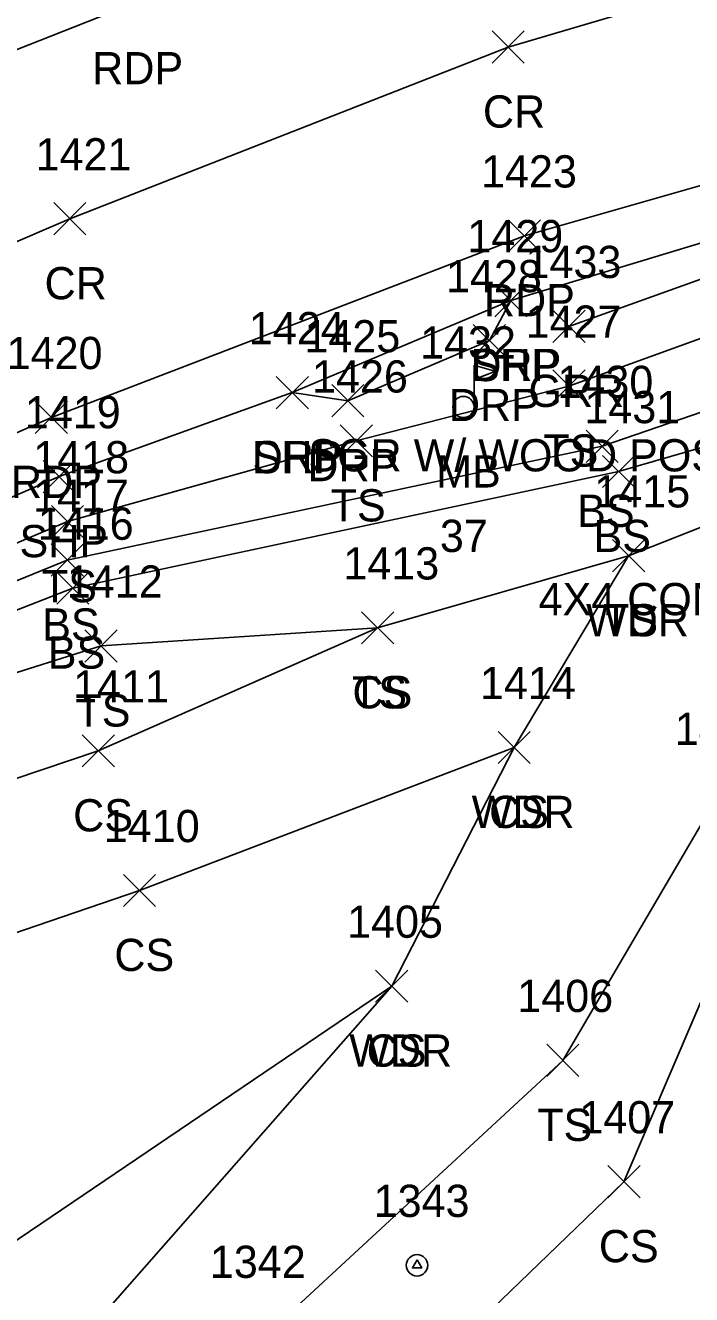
# Model space of a CAD drawing. Extents: x 1606530 to 1613020, y 784959 to 789666.
# Drawn here: x 1609059.8 to 1609101.2, y 788335.5 to 788414.2 of the extents above; entities that cross this region are included whole.
import ezdxf

# ---------------------------------------------------------------- set-up
doc = ezdxf.new("R2010")
doc.units = 0
for name, color, linetype in [('L_A', 7, 'Continuous'), ('L_C', 7, 'Continuous'), ('L_I', 7, 'Continuous'), ('L_TIC', 7, 'Continuous'), ('LAWA', 7, 'Continuous'), ('LELB', 7, 'Continuous'), ('LMB', 7, 'Continuous'), ('M_C', 7, 'Continuous'), ('M_I', 7, 'Continuous'), ('MPIR', 7, 'Continuous'), ('P_A', 7, 'Continuous'), ('P_I', 7, 'Continuous'), ('P_TIC', 7, 'Continuous'), ('PET', 7, 'Continuous'), ('PRC', 7, 'Continuous'), ('PSP', 7, 'Continuous'), ('R_A', 7, 'Continuous'), ('R_C', 7, 'Continuous'), ('R_I', 7, 'Continuous'), ('R_TIC', 7, 'Continuous'), ('RDP', 7, 'Continuous'), ('RGR', 7, 'Continuous')]:
    doc.layers.add(name, color=color, linetype=linetype)

msp = doc.modelspace()

# ---------------------------------------------------------------- linework, layer by layer
at = {"layer": 'L_TIC'}
for points in [[(1609092.562, 788390.85), (1609094.562, 788392.85)], [(1609094.562, 788390.85), (1609092.562, 788392.85)], [(1609079.361, 788387.448), (1609081.361, 788389.448)], [(1609081.361, 788387.448), (1609079.361, 788389.448)], [(1609094.627, 788387.111), (1609096.627, 788389.111)], [(1609096.627, 788387.111), (1609094.627, 788389.111)], [(1609095.646, 788385.547), (1609097.646, 788387.547)], [(1609097.646, 788385.547), (1609095.646, 788387.547)], [(1609061.434, 788382.436), (1609063.434, 788384.436)], [(1609063.434, 788382.436), (1609061.434, 788384.436)], [(1609061.425, 788380.051), (1609063.425, 788382.051)], [(1609063.425, 788380.051), (1609061.425, 788382.051)], [(1609096.263, 788380.318), (1609098.263, 788382.318)], [(1609098.263, 788380.318), (1609096.263, 788382.318)], [(1609096.263, 788380.318), (1609098.263, 788382.318)], [(1609098.263, 788380.318), (1609096.263, 788382.318)], [(1609061.769, 788378.31), (1609063.769, 788380.31)], [(1609063.769, 788378.31), (1609061.769, 788380.31)], [(1609080.683, 788375.845), (1609082.683, 788377.845)], [(1609082.683, 788375.845), (1609080.683, 788377.845)], [(1609080.683, 788375.845), (1609082.683, 788377.845)], [(1609082.683, 788375.845), (1609080.683, 788377.845)], [(1609063.518, 788374.718), (1609065.518, 788376.718)], [(1609065.518, 788374.718), (1609063.518, 788376.718)], [(1609063.344, 788368.211), (1609065.344, 788370.211)], [(1609065.344, 788368.211), (1609063.344, 788370.211)], [(1609089.163, 788368.421), (1609091.163, 788370.421)], [(1609091.163, 788368.421), (1609089.163, 788370.421)], [(1609089.163, 788368.421), (1609091.163, 788370.421)], [(1609091.163, 788368.421), (1609089.163, 788370.421)], [(1609065.903, 788359.544), (1609067.903, 788361.544)], [(1609067.903, 788359.544), (1609065.903, 788361.544)], [(1609081.563, 788353.607), (1609083.563, 788355.607)], [(1609083.563, 788353.607), (1609081.563, 788355.607)], [(1609081.563, 788353.607), (1609083.563, 788355.607)], [(1609083.563, 788353.607), (1609081.563, 788355.607)], [(1609092.182, 788349), (1609094.182, 788351)], [(1609094.182, 788349), (1609092.182, 788351)], [(1609095.979, 788341.471), (1609097.979, 788343.471)], [(1609097.979, 788341.471), (1609095.979, 788343.471)]]:
    msp.add_lwpolyline(points, dxfattribs=at)
at = {"layer": 'LAWA'}
msp.add_lwpolyline([(1609030.558, 788292.644), (1609056.025, 788324.438), (1609082.563, 788354.607), (1609090.163, 788369.421), (1609097.263, 788381.318), (1609109.225, 788386.029), (1609115.481, 788389.157), (1609124.652, 788392.268), (1609168.817, 788397.242), (1609199.024, 788403.22), (1609247.618, 788406.183), (1609289.075, 788410.022), (1609331.313, 788409.888), (1609380.075, 788411.965), (1609422.468, 788410.639), (1609441.897, 788412.637), (1609456.944, 788393.193), (1609459.972, 788389.839), (1609451.94, 788379.298), (1609445.608, 788371.597)], dxfattribs=at)
at = {"layer": 'LELB'}
for points in [[(1608830.696, 788263.063), (1608870.165, 788285.39), (1608903.607, 788303.663), (1608913.174, 788310.86), (1608944.686, 788327.514), (1608982.087, 788348.333), (1609025.652, 788367.839), (1609062.434, 788383.436), (1609080.361, 788388.448), (1609093.562, 788391.85), (1609111.494, 788398.335), (1609124.294, 788403.549), (1609165.327, 788413.887), (1609196.534, 788419.382), (1609241.91, 788424.939), (1609287.826, 788428.62), (1609331.16, 788428.802), (1609379.004, 788428.227), (1609424.692, 788425.716), (1609443.901, 788424.449), (1609475.845, 788418.568), (1609486.477, 788419.986), (1609502.626, 788421.703)], [(1608831.711, 788260.016), (1608870.917, 788283.544), (1608902.903, 788300.531), (1608905.174, 788302.06), (1608913.863, 788309.861), (1608916.937, 788311.145), (1608945.63, 788325.493), (1608982.977, 788345.361), (1609026.683, 788366.486), (1609062.425, 788381.051), (1609095.627, 788388.111), (1609108.106, 788392.394), (1609116.71, 788392.112), (1609124.652, 788392.268)], [(1608916.937, 788311.145), (1608917.754, 788309.334), (1608946.535, 788323.696), (1608983.532, 788344.076), (1609027.167, 788365.399), (1609062.769, 788379.31), (1609096.646, 788386.547), (1609108.627, 788390.006), (1609115.481, 788389.157)], [(1609044.685, 788283.597), (1609058.258, 788305.111), (1609096.979, 788342.471), (1609105.849, 788363.204), (1609115.481, 788389.157)], [(1609038.437, 788287.942), (1609056.526, 788316.096), (1609093.182, 788350), (1609102.909, 788366.579), (1609109.225, 788386.029)], [(1608913.174, 788310.86), (1608913.863, 788309.861), (1608915.932, 788307.405), (1608919.354, 788304.61), (1608948.758, 788319.84), (1608984.788, 788341.433), (1609027.872, 788364.143), (1609064.518, 788375.718), (1609081.683, 788376.845), (1609097.263, 788381.318)], [(1608906.345, 788297.69), (1608919.354, 788304.61), (1608926.596, 788300.128), (1608951.558, 788313.661), (1608958.57, 788316.223), (1608987.922, 788332.405), (1609030.947, 788357.96), (1609064.344, 788369.211), (1609081.683, 788376.845)], [(1608853.861, 788253.713), (1608879.114, 788266.692), (1608889.068, 788272.674), (1608908.345, 788283.283), (1608917.542, 788288.203), (1608929.967, 788294.463), (1608949.674, 788303.496), (1608962.876, 788306.16), (1608991.964, 788321.509), (1609035.123, 788349.675), (1609066.903, 788360.544), (1609090.163, 788369.421)], [(1608971.317, 788290.189), (1608998.987, 788305.086), (1609044.225, 788328.655), (1609082.563, 788354.607)]]:
    msp.add_lwpolyline(points, dxfattribs=at)
at = {"layer": 'LMB'}
for p, q in [((1609087.664, 788393.154), (1609088.958, 788392.772)), ((1609087.67, 788390.562), (1609087.669, 788393.157)), ((1609087.669, 788392.255), (1609088.952, 788392.763)), ((1609087.014, 788390.554), (1609087.014, 788390.554))]:
    msp.add_line(p, q, dxfattribs=at)
msp.add_circle((1609087.014, 788390.553), 0.656, dxfattribs=at)
at = {"layer": 'MPIR'}
msp.add_lwpolyline([(1609084.131, 788337.614), (1609083.843, 788337.114), (1609084.42, 788337.114)], close=True, dxfattribs=at)
msp.add_circle((1609084.131, 788337.281), 0.667, dxfattribs=at)
at = {"layer": 'P_TIC'}
for points in [[(1609088.789, 788411.891), (1609090.789, 788413.891)], [(1609090.789, 788411.891), (1609088.789, 788413.891)], [(1609061.579, 788401.235), (1609063.579, 788403.235)], [(1609063.579, 788401.235), (1609061.579, 788403.235)], [(1609089.798, 788400.175), (1609091.798, 788402.175)], [(1609091.798, 788400.175), (1609089.798, 788402.175)], [(1609088.956, 788396.157), (1609090.956, 788398.157)], [(1609090.956, 788396.157), (1609088.956, 788398.157)], [(1609075.386, 788390.443), (1609077.386, 788392.443)], [(1609077.386, 788390.443), (1609075.386, 788392.443)], [(1609060.437, 788388.904), (1609062.437, 788390.904)], [(1609062.437, 788388.904), (1609060.437, 788390.904)], [(1609060.921, 788385.228), (1609062.921, 788387.228)], [(1609062.921, 788385.228), (1609060.921, 788387.228)]]:
    msp.add_lwpolyline(points, dxfattribs=at)
at = {"layer": 'PET'}
for points in [[(1608827.199, 788266.245), (1608867.859, 788290.541), (1608906.681, 788312.856), (1608942.677, 788332.755), (1608980.541, 788352.164), (1609023.571, 788373.225), (1609061.437, 788389.904), (1609090.798, 788401.175), (1609121.915, 788410.089), (1609165.169, 788419.998), (1609195.853, 788425.54), (1609240.139, 788431.13), (1609287.877, 788434.372), (1609331.481, 788435.115), (1609378.889, 788434.051), (1609425.427, 788432.251), (1609443.83, 788431.331), (1609477.321, 788429.782), (1609518.441, 788427.602), (1609569.185, 788424.684), (1609602.993, 788422.58), (1609641.45, 788420.372), (1609681.697, 788417.919), (1609727.381, 788415.531)], [(1608858.102, 788310.732), (1608896.559, 788332.458), (1608932.583, 788352.682), (1608960.396, 788367.207), (1608987.919, 788381.261), (1609019.358, 788396.212), (1609040.554, 788405.359), (1609066.482, 788415.581), (1609102.049, 788427.759), (1609127.707, 788434.803)]]:
    msp.add_lwpolyline(points, dxfattribs=at)
at = {"layer": 'PRC'}
msp.add_lwpolyline([(1608863.252, 788300.903), (1608901.811, 788322.596), (1608937.609, 788342.722), (1608976.118, 788362.757), (1609017.577, 788382.951), (1609062.579, 788402.235), (1609089.789, 788412.891), (1609118.805, 788421.444), (1609162.845, 788431.752), (1609194.146, 788437.356), (1609237.64, 788442.85), (1609286.897, 788446.16), (1609332.711, 788446.436), (1609379.393, 788445.342), (1609425.621, 788443.432), (1609445.831, 788442.47), (1609477.779, 788440.947), (1609519.757, 788438.847), (1609569.723, 788435.898), (1609601.73, 788434.311), (1609642.39, 788431.817), (1609682.025, 788429.153), (1609726.546, 788426.785)], dxfattribs=at)
at = {"layer": 'PSP'}
msp.add_lwpolyline([(1608830.356, 788264.996), (1608869.22, 788287.395), (1608908.593, 788309.539), (1608943.858, 788329.41), (1608981.495, 788349.27), (1609025.121, 788370.206), (1609061.921, 788386.228), (1609076.386, 788391.443), (1609089.956, 788397.157), (1609122.924, 788407.129), (1609165.713, 788417.027), (1609196.423, 788422.444), (1609241.306, 788428.683), (1609287.876, 788431.577), (1609331.197, 788431.668), (1609378.916, 788430.276), (1609425.006, 788428.307)], dxfattribs=at)
at = {"layer": 'R_TIC'}
for points in [[(1609088.956, 788396.157), (1609090.956, 788398.157)], [(1609090.956, 788396.157), (1609088.956, 788398.157)], [(1609092.559, 788394.554), (1609094.559, 788396.554)], [(1609094.559, 788394.554), (1609092.559, 788396.554)], [(1609087.624, 788393.678), (1609089.624, 788395.678)], [(1609089.624, 788393.678), (1609087.624, 788395.678)], [(1609075.386, 788390.443), (1609077.386, 788392.443)], [(1609077.386, 788390.443), (1609075.386, 788392.443)], [(1609078.835, 788389.944), (1609080.835, 788391.944)], [(1609080.835, 788389.944), (1609078.835, 788391.944)]]:
    msp.add_lwpolyline(points, dxfattribs=at)
at = {"layer": 'RDP'}
msp.add_lwpolyline([(1609076.386, 788391.443), (1609079.835, 788390.944), (1609088.624, 788394.678), (1609089.956, 788397.157)], dxfattribs=at)
at = {"layer": 'RGR'}
msp.add_lwpolyline([(1609093.559, 788395.554), (1609123.333, 788406.226), (1609196.194, 788421.651), (1609241.24, 788427.813), (1609287.728, 788430.927), (1609331.285, 788431.083), (1609378.856, 788429.586), (1609425.051, 788427.72), (1609442.608, 788426.228), (1609477.202, 788421.475)], dxfattribs=at)

# ---------------------------------------------------------------- texts
at = {"layer": 'L_A'}
for s, p in [('TS', (1609091.972, 788386.85)), ('MB', (1609085.321, 788385.553)), ('TS', (1609078.77, 788383.448)), ('BS', (1609094.068, 788383.111)), ('BS', (1609095.087, 788381.547)), ('TS', (1609060.844, 788378.436)), ('BS', (1609060.866, 788376.051)), ('WDR', (1609094.626, 788376.318)), ('TS', (1609095.673, 788376.318)), ('BS', (1609061.21, 788374.31)), ('TS', (1609080.093, 788371.845)), ('CS', (1609080.124, 788371.845)), ('TS', (1609062.928, 788370.718)), ('WDR', (1609087.525, 788364.421)), ('CS', (1609088.604, 788364.421)), ('CS', (1609062.785, 788364.211)), ('CS', (1609065.344, 788355.544)), ('WDR', (1609079.926, 788349.607)), ('CS', (1609081.004, 788349.607)), ('TS', (1609091.592, 788345)), ('CS', (1609095.42, 788337.471))]:
    msp.add_text(s, height=2, dxfattribs=at).set_placement(p)
at = {"layer": 'L_C'}
msp.add_text('37', height=2, dxfattribs=at).set_placement((1609085.55, 788381.553))
at = {"layer": 'L_I'}
for s, p in [('1427', (1609090.87, 788394.85)), ('1432', (1609084.322, 788393.553)), ('1426', (1609077.613, 788391.448)), ('1430', (1609092.847, 788391.111)), ('1431', (1609094.52, 788389.547)), ('1418', (1609060.308, 788386.436)), ('1417', (1609060.299, 788384.051)), ('1415', (1609095.138, 788384.318)), ('1415', (1609095.138, 788384.318)), ('1416', (1609060.589, 788382.31)), ('1413', (1609079.558, 788379.845)), ('1413', (1609079.558, 788379.845)), ('1412', (1609062.393, 788378.718)), ('1411', (1609062.785, 788372.211)), ('1414', (1609088.037, 788372.421)), ('1414', (1609088.037, 788372.421)), ('1409', (1609100.13, 788369.579)), ('1410', (1609064.691, 788363.544)), ('1405', (1609079.792, 788357.607)), ('1405', (1609079.792, 788357.607)), ('1406', (1609090.356, 788353)), ('1407', (1609094.208, 788345.471))]:
    msp.add_text(s, height=2, dxfattribs=at).set_placement(p)
at = {"layer": 'M_C'}
msp.add_text("4X4 CONC 1' ABGS DISTURBED", height=2, dxfattribs=at).set_placement((1609091.677, 788377.629))
at = {"layer": 'M_I'}
for s, p in [('1343', (1609081.439, 788340.281)), ('1342', (1609071.273, 788336.501))]:
    msp.add_text(s, height=2, dxfattribs=at).set_placement(p)
at = {"layer": 'P_A'}
for s, p in [('RDP', (1609063.97, 788410.581)), ('CR', (1609088.222, 788407.891)), ('CR', (1609061.012, 788397.235)), ('RDP', (1609088.286, 788396.175)), ('SHP', (1609087.492, 788392.157)), ('SHP', (1609073.921, 788386.443)), ('RDP', (1609058.925, 788384.904)), ('SHP', (1609059.457, 788381.228))]:
    msp.add_text(s, height=2, dxfattribs=at).set_placement(p)
at = {"layer": 'P_I'}
for s, p in [('1421', (1609060.453, 788405.235)), ('1423', (1609088.105, 788404.175)), ('1429', (1609087.256, 788400.157)), ('1424', (1609073.693, 788394.443)), ('1420', (1609058.658, 788392.904)), ('1419', (1609059.788, 788389.228))]:
    msp.add_text(s, height=2, dxfattribs=at).set_placement(p)
at = {"layer": 'R_A'}
for s, p in [('DRP', (1609087.444, 788392.157)), ('GRR', (1609091.048, 788390.554)), ('DRP', (1609086.112, 788389.678)), ('DRP', (1609073.874, 788386.443)), ('DRP', (1609077.323, 788385.944))]:
    msp.add_text(s, height=2, dxfattribs=at).set_placement(p)
at = {"layer": 'R_C'}
msp.add_text('SGR W/ WOOD POSTS', height=2, dxfattribs=at).set_placement((1609077.386, 788386.554))
at = {"layer": 'R_I'}
for s, p in [('1429', (1609087.256, 788400.157)), ('1433', (1609090.867, 788398.554)), ('1428', (1609085.931, 788397.678)), ('1424', (1609073.693, 788394.443)), ('1425', (1609077.142, 788393.944))]:
    msp.add_text(s, height=2, dxfattribs=at).set_placement(p)

doc.saveas('drawing.dxf')
